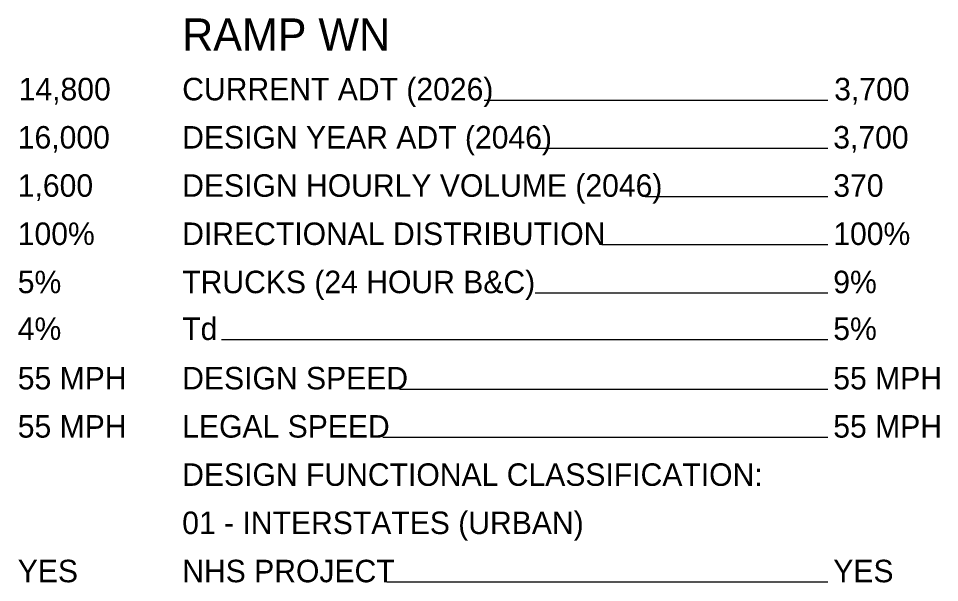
# Model space of a CAD drawing. Extents: x 0 to 34, y -1.2 to 22.
# Drawn here: x 6.05 to 11.78, y 6.64 to 10.15 of the extents above; entities that cross this region are included whole.
import ezdxf

# ---------------------------------------------------------------- set-up
doc = ezdxf.new("R2010")
doc.units = 0
doc.layers.add('SH_Cut_Line', color=7, linetype='Continuous')
doc.layers.add('SH_Data', color=7, linetype='Continuous')

msp = doc.modelspace()

# ---------------------------------------------------------------- linework, layer by layer
at = {"layer": 'SH_Data'}
for p, q in [((11.0803, 9.6429), (8.9422, 9.6429)), ((11.0803, 9.3429), (9.2597, 9.3429)), ((11.0803, 9.0429), (9.9435, 9.0429)), ((11.0803, 8.7429), (9.6749, 8.7429)), ((11.0803, 8.4429), (9.2597, 8.4429)), ((11.0803, 8.1519), (7.3097, 8.1519)), ((11.0803, 7.8442), (8.4171, 7.8442)), ((11.0803, 7.5442), (8.3134, 7.5442)), ((11.0803, 6.6442), (8.3381, 6.6442))]:
    msp.add_line(p, q, dxfattribs=at)

# ---------------------------------------------------------------- texts
at = {"layer": 'SH_Cut_Line'}
for s, height, p in [('RAMP WN', 0.2, (7.0656, 9.9527)), ('14,800', 0.14, (6.0486, 9.6429)), ('CURRENT ADT (2026)', 0.14, (7.0656, 9.6429)), ('3,700', 0.14, (11.1197, 9.6429)), ('16,000', 0.14, (6.043, 9.3429)), ('DESIGN YEAR ADT (2046)', 0.14, (7.0656, 9.3429)), ('3,700', 0.14, (11.1141, 9.3429)), ('1,600', 0.14, (6.043, 9.0429)), ('DESIGN HOURLY VOLUME (2046)', 0.14, (7.0656, 9.0429)), ('370', 0.14, (11.1141, 9.0429)), ('100%', 0.14, (6.043, 8.7429)), ('DIRECTIONAL DISTRIBUTION', 0.14, (7.0656, 8.7429)), ('100%', 0.14, (11.1141, 8.7429)), ('5%', 0.14, (6.043, 8.4429)), ('TRUCKS (24 HOUR B&C)', 0.14, (7.0656, 8.4429)), ('9%', 0.14, (11.1141, 8.4429)), ('4%', 0.14, (6.043, 8.1519)), ('Td', 0.14, (7.0656, 8.1519)), ('5%', 0.14, (11.1141, 8.1519)), ('55 MPH', 0.14, (6.043, 7.8442)), ('DESIGN SPEED', 0.14, (7.0656, 7.8442)), ('55 MPH', 0.14, (11.1141, 7.8442)), ('55 MPH', 0.14, (6.043, 7.5442)), ('LEGAL SPEED', 0.14, (7.0656, 7.5442)), ('55 MPH', 0.14, (11.1141, 7.5442)), ('DESIGN FUNCTIONAL CLASSIFICATION:', 0.14, (7.0656, 7.2442)), ('01 - INTERSTATES (URBAN)', 0.14, (7.0656, 6.9442)), ('YES', 0.14, (6.043, 6.6442)), ('NHS PROJECT', 0.14, (7.0656, 6.6442)), ('YES', 0.14, (11.1141, 6.6442))]:
    msp.add_text(s, height=height, dxfattribs=at).set_placement(p)

doc.saveas('drawing.dxf')
